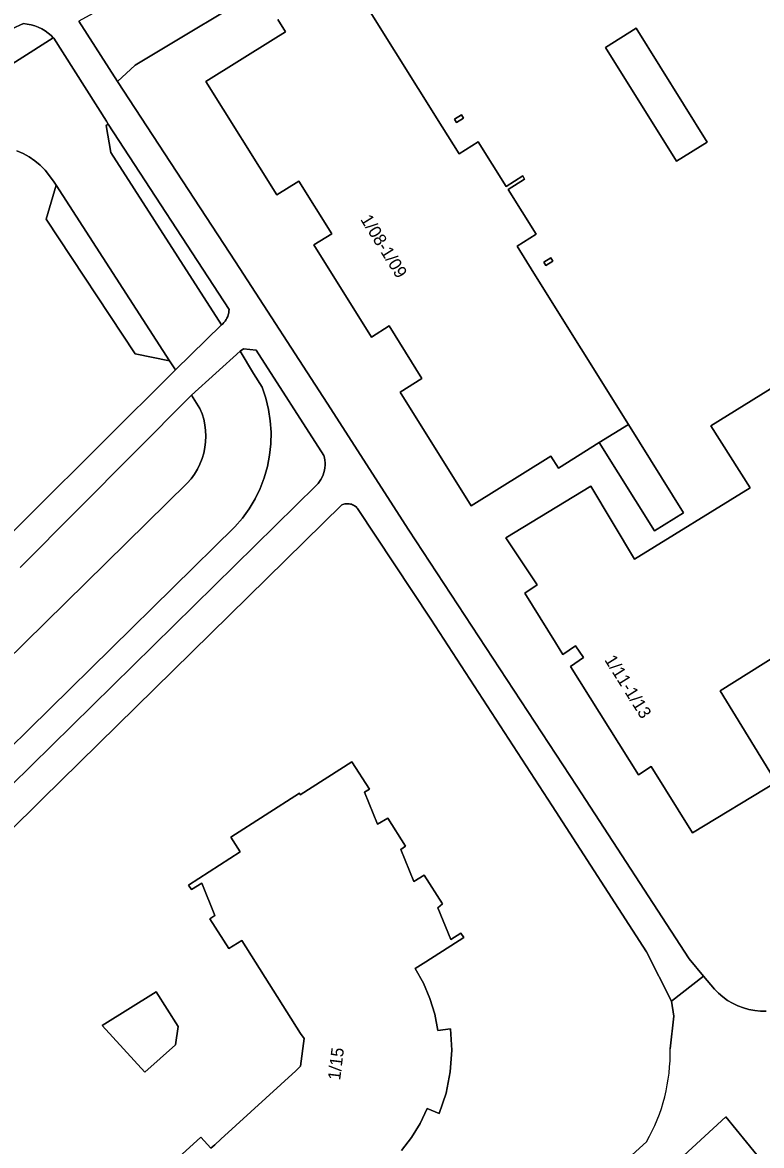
# Model space of a CAD drawing. Extents: x 162788 to 163838, y 385791 to 386523.
# Drawn here: x 163143.1 to 163202.2, y 386088.7 to 386178.4 of the extents above; entities that cross this region are included whole.
import ezdxf

# ---------------------------------------------------------------- set-up
doc = ezdxf.new("R2010")
doc.units = 0
for name, color, linetype in [('IMGEO_Berm_groen', 7, 'Continuous'), ('IMGEO_Erf', 7, 'Continuous'), ('IMGEO_Grasland_overig', 7, 'Continuous'), ('IMGEO_Pand', 7, 'Continuous'), ('IMGEO_Pand_nummerreeks', 7, 'Continuous'), ('IMGEO_Parkeervlak_open', 7, 'Continuous'), ('IMGEO_Rijbaan_lokaal_gesloten', 7, 'Continuous'), ('IMGEO_Woonerf_gesloten', 7, 'Continuous'), ('IMGEO_Woonerf_open', 7, 'Continuous')]:
    doc.layers.add(name, color=color, linetype=linetype)

msp = doc.modelspace()

# ---------------------------------------------------------------- linework, layer by layer
at = {"layer": 'IMGEO_Berm_groen'}
msp.add_lwpolyline([(163149.982, 386170.293), (163149.802, 386170.175), (163150.188, 386168.025), (163159.018, 386154.239), (163159.126, 386154.334), (163159.226, 386154.437), (163159.316, 386154.549), (163159.395, 386154.669), (163159.464, 386154.795), (163159.521, 386154.927), (163159.566, 386155.063), (163159.599, 386155.203), (163159.619, 386155.345), (163159.627, 386155.489)], close=True, dxfattribs=at)
for points in [[(163135.695, 386111.044), (163166.602, 386141.424), (163166.739, 386141.57), (163166.863, 386141.727), (163166.974, 386141.894), (163167.069, 386142.069), (163167.15, 386142.253), (163167.214, 386142.442), (163167.262, 386142.636), (163167.293, 386142.834), (163167.307, 386143.034), (163167.305, 386143.234), (163167.285, 386143.433), (163167.248, 386143.629), (163167.195, 386143.822), (163161.786, 386152.232), (163160.792, 386152.325), (163160.511, 386152.137), (163161.586, 386150.349), (163162.28, 386149.265), (163162.573, 386148.391), (163162.789, 386147.496), (163162.928, 386146.585), (163162.987, 386145.665), (163162.968, 386144.743), (163162.869, 386143.827), (163162.691, 386142.923), (163162.437, 386142.037), (163162.107, 386141.177), (163161.705, 386140.347), (163161.232, 386139.556), (163160.694, 386138.808), (163160.093, 386138.11), (163135.419, 386113.879)], [(163123.874, 386109.738), (163156.292, 386141.593), (163156.591, 386141.944), (163156.86, 386142.318), (163157.097, 386142.714), (163157.301, 386143.128), (163157.47, 386143.558), (163157.603, 386143.999), (163157.698, 386144.449), (163157.756, 386144.905), (163157.775, 386145.362), (163157.756, 386145.818), (163157.699, 386146.27), (163157.603, 386146.713), (163157.471, 386147.144), (163157.302, 386147.561), (163156.619, 386148.636), (163142.941, 386134.855)]]:
    msp.add_lwpolyline(points, dxfattribs=at)
at = {"layer": 'IMGEO_Erf'}
for points in [[(163174.351, 386188.349), (163152.119, 386175.015), (163150.727, 386173.684), (163160.137, 386159.282), (163167.48, 386147.987), (163174, 386137.852), (163187.423, 386117.375), (163196.406, 386103.576), (163197.553, 386102.198), (163198.412, 386101.166), (163198.74, 386100.837), (163199.095, 386100.537), (163199.475, 386100.269), (163199.876, 386100.033), (163200.296, 386099.833), (163200.731, 386099.67), (163201.178, 386099.544), (163201.635, 386099.457), (163202.097, 386099.409), (163202.562, 386099.401)], [(163169.112, 386182.147), (163176.671, 386170.084), (163178.028, 386167.918), (163179.55, 386168.873), (163181.774, 386165.309), (163183.101, 386166.149), (163183.247, 386165.899), (163181.929, 386165.064), (163184.16, 386161.485), (163182.654, 386160.532), (163183.998, 386158.378), (163191.539, 386146.293), (163195.946, 386139.231), (163193.633, 386137.784), (163189.218, 386144.841), (163185.946, 386142.794), (163185.335, 386143.768), (163178.973, 386139.791), (163173.302, 386148.859), (163175.048, 386149.951), (163172.438, 386154.158), (163171.012, 386153.268), (163166.412, 386160.64), (163167.837, 386161.529), (163165.202, 386165.721), (163163.456, 386164.629), (163157.776, 386173.707), (163163.154, 386177.061), (163164.137, 386177.674), (163163.53, 386178.648)], [(163137.817, 386133.231), (163155.341, 386150.644), (163154.867, 386151.379), (163152.129, 386151.937), (163145.02, 386162.683), (163145.808, 386165.423), (163145.612, 386165.726), (163144.927, 386166.624), (163144.534, 386167.01), (163144.109, 386167.36), (163143.655, 386167.671), (163143.176, 386167.941), (163142.674, 386168.168)], [(163207.82, 386130.622), (163198.88, 386125.005), (163203.35, 386117.7), (163196.672, 386113.666), (163193.356, 386118.946), (163192.347, 386118.294), (163186.911, 386126.96), (163187.943, 386127.659), (163187.326, 386128.598), (163186.314, 386127.919), (163185.726, 386128.862), (163183.269, 386132.801), (163184.264, 386133.48), (163181.739, 386137.238), (163188.543, 386141.352), (163192.027, 386135.514), (163201.283, 386141.237), (163198.119, 386146.168), (163204.791, 386150.309)], [(163194.877, 386096.402), (163195.179, 386099.002), (163194.99, 386100.199), (163192.996, 386104.134), (163185.454, 386115.822), (163175.748, 386130.733), (163169.9, 386139.568), (163169.843, 386139.633), (163169.781, 386139.694), (163169.715, 386139.75), (163169.643, 386139.799), (163169.568, 386139.843), (163169.489, 386139.879), (163169.408, 386139.909), (163169.324, 386139.932), (163169.239, 386139.948), (163169.152, 386139.957), (163169.066, 386139.958), (163168.979, 386139.952), (163168.893, 386139.939), (163168.809, 386139.918), (163168.727, 386139.891), (163168.647, 386139.856), (163144.69, 386116.333), (163116.889, 386088.826)], [(163155.599, 386087.705), (163157.375, 386089.331), (163158.182, 386088.45), (163158.481, 386088.723), (163158.978, 386089.177), (163164.955, 386094.645), (163165.343, 386095), (163165.62, 386097.207), (163165.352, 386097.62), (163160.644, 386105.045), (163159.621, 386104.421), (163158.103, 386106.796), (163158.496, 386107.051), (163157.447, 386109.635), (163156.618, 386109.126), (163156.397, 386109.483), (163160.515, 386112.142), (163159.769, 386113.313), (163165.255, 386116.817), (163165.303, 386116.703), (163169.449, 386119.331), (163170.856, 386117.142), (163170.453, 386116.896), (163171.504, 386114.352), (163172.318, 386114.817), (163173.732, 386112.592), (163173.353, 386112.334), (163174.401, 386109.77), (163175.218, 386110.268), (163176.69, 386107.982), (163176.304, 386107.663), (163177.351, 386105.139), (163178.156, 386105.644), (163178.394, 386105.293), (163175.367, 386103.35), (163174.512, 386102.801), (163175.162, 386101.65), (163175.685, 386100.428), (163176.07, 386099.155), (163176.31, 386097.855), (163177.333, 386098.001), (163177.427, 386096.286), (163177.305, 386094.559), (163176.969, 386092.861), (163176.428, 386091.231), (163175.475, 386091.614), (163174.914, 386090.429), (163174.223, 386089.306), (163173.413, 386088.264)], [(163129.316, 386031.834), (163130.711, 386032.995), (163156.731, 386056.38), (163168.437, 386066.688), (163193.001, 386088.975)]]:
    msp.add_lwpolyline(points, dxfattribs=at)
for points in [[(163197.834, 386168.858), (163195.392, 386167.335), (163189.725, 386176.426), (163192.167, 386177.948)], [(163178.365, 386170.754), (163177.803, 386170.416), (163177.635, 386170.688), (163178.2, 386171.037)], [(163185.516, 386159.33), (163184.953, 386158.995), (163184.786, 386159.268), (163185.347, 386159.61)], [(163149.491, 386098.267), (163153.804, 386100.948), (163155.569, 386098.189), (163155.34, 386096.714), (163152.891, 386094.531)]]:
    msp.add_lwpolyline(points, close=True, dxfattribs=at)
msp.add_arc((163180.704, 386096.032), 14.178, 330.15093, 1.49721, dxfattribs=at)
at = {"layer": 'IMGEO_Grasland_overig'}
msp.add_lwpolyline([(163105.896, 385959.534), (163111.404, 385963.758), (163130.396, 385976.293), (163134.062, 385978.713), (163159.928, 385999.607), (163159.543, 386000), (163138.447, 386021.548), (163206.371, 386083.102), (163206.676, 386083.379), (163205.132, 386083.984), (163204.985, 386084.042), (163200.984, 386088.924), (163199.323, 386090.951), (163185.549, 386078.284), (163151.762, 386047.67), (163133.296, 386031.516)], dxfattribs=at)
at = {"layer": 'IMGEO_Pand'}
for points in [[(163163.53, 386178.648), (163164.137, 386177.674), (163163.154, 386177.061), (163157.776, 386173.707), (163163.456, 386164.629), (163165.202, 386165.721), (163167.837, 386161.529), (163166.412, 386160.64), (163171.012, 386153.268), (163172.438, 386154.158), (163175.048, 386149.951), (163173.302, 386148.859), (163178.973, 386139.791), (163185.335, 386143.768), (163185.946, 386142.794), (163189.218, 386144.841), (163191.539, 386146.293), (163183.998, 386158.378), (163182.654, 386160.532), (163184.16, 386161.485), (163181.929, 386165.064), (163183.247, 386165.899), (163183.101, 386166.149), (163181.774, 386165.309), (163179.55, 386168.873), (163178.028, 386167.918), (163176.671, 386170.084), (163169.112, 386182.147)], [(163204.791, 386150.309), (163198.119, 386146.168), (163201.283, 386141.237), (163192.027, 386135.514), (163188.543, 386141.352), (163181.739, 386137.238), (163184.264, 386133.48), (163183.269, 386132.801), (163185.726, 386128.862), (163186.314, 386127.919), (163187.326, 386128.598), (163187.943, 386127.659), (163186.911, 386126.96), (163192.347, 386118.294), (163193.356, 386118.946), (163196.672, 386113.666), (163203.35, 386117.7), (163198.88, 386125.005), (163207.82, 386130.622)], [(163173.413, 386088.264), (163174.223, 386089.306), (163174.914, 386090.429), (163175.475, 386091.614), (163176.428, 386091.231), (163176.969, 386092.861), (163177.305, 386094.559), (163177.427, 386096.286), (163177.333, 386098.001), (163176.31, 386097.855), (163176.07, 386099.155), (163175.685, 386100.428), (163175.162, 386101.65), (163174.512, 386102.801), (163175.367, 386103.35), (163178.394, 386105.293), (163178.156, 386105.644), (163177.351, 386105.139), (163176.304, 386107.663), (163176.69, 386107.982), (163175.218, 386110.268), (163174.401, 386109.77), (163173.353, 386112.334), (163173.732, 386112.592), (163172.318, 386114.817), (163171.504, 386114.352), (163170.453, 386116.896), (163170.856, 386117.142), (163169.449, 386119.331), (163165.303, 386116.703), (163165.255, 386116.817), (163159.769, 386113.313), (163160.515, 386112.142), (163156.397, 386109.483), (163156.618, 386109.126), (163157.447, 386109.635), (163158.496, 386107.051), (163158.103, 386106.796), (163159.621, 386104.421), (163160.644, 386105.045), (163165.352, 386097.62), (163165.62, 386097.207), (163165.343, 386095), (163164.955, 386094.645), (163158.978, 386089.177), (163158.481, 386088.723), (163158.182, 386088.45), (163157.375, 386089.331), (163155.599, 386087.705)]]:
    msp.add_lwpolyline(points, dxfattribs=at)
for points in [[(163189.725, 386176.426), (163195.392, 386167.335), (163197.834, 386168.858), (163192.167, 386177.948)], [(163178.365, 386170.754), (163178.2, 386171.037), (163177.635, 386170.688), (163177.803, 386170.416)], [(163185.516, 386159.33), (163185.347, 386159.61), (163184.786, 386159.268), (163184.953, 386158.995)], [(163191.539, 386146.293), (163189.218, 386144.841), (163193.633, 386137.784), (163195.946, 386139.231)], [(163155.34, 386096.714), (163155.569, 386098.189), (163153.804, 386100.948), (163149.491, 386098.267), (163152.891, 386094.531)]]:
    msp.add_lwpolyline(points, close=True, dxfattribs=at)
at = {"layer": 'IMGEO_Parkeervlak_open'}
msp.add_lwpolyline([(163145.808, 386165.423), (163145.02, 386162.683), (163152.129, 386151.937), (163154.867, 386151.379)], close=True, dxfattribs=at)
at = {"layer": 'IMGEO_Rijbaan_lokaal_gesloten'}
for points in [[(163202.562, 386099.401), (163202.097, 386099.409), (163201.635, 386099.457), (163201.178, 386099.544), (163200.731, 386099.67), (163200.296, 386099.833), (163199.876, 386100.033), (163199.475, 386100.269), (163199.095, 386100.537), (163198.74, 386100.837), (163198.412, 386101.166), (163197.553, 386102.198), (163194.99, 386100.199), (163195.179, 386099.002), (163194.877, 386096.402)], [(163185.549, 386078.284), (163199.323, 386090.951), (163200.984, 386088.924), (163204.985, 386084.042)], [(163193.001, 386088.975), (163168.437, 386066.688), (163156.731, 386056.38), (163130.711, 386032.995), (163129.316, 386031.834)]]:
    msp.add_lwpolyline(points, dxfattribs=at)
msp.add_arc((163180.704, 386096.032), 14.178, 330.15093, 1.49721, dxfattribs=at)
at = {"layer": 'IMGEO_Woonerf_gesloten'}
for points in [[(163116.889, 386088.826), (163144.69, 386116.333), (163168.647, 386139.856), (163168.727, 386139.891), (163168.809, 386139.918), (163168.893, 386139.939), (163168.979, 386139.952), (163169.066, 386139.958), (163169.152, 386139.957), (163169.239, 386139.948), (163169.324, 386139.932), (163169.408, 386139.909), (163169.489, 386139.879), (163169.568, 386139.843), (163169.643, 386139.799), (163169.715, 386139.75), (163169.781, 386139.694), (163169.843, 386139.633), (163169.9, 386139.568), (163175.748, 386130.733), (163185.454, 386115.822), (163192.996, 386104.134), (163194.99, 386100.199), (163197.553, 386102.198), (163196.406, 386103.576), (163187.423, 386117.375), (163174, 386137.852), (163167.48, 386147.987), (163160.137, 386159.282), (163150.727, 386173.684), (163147.636, 386178.505)], [(163140.387, 386177.042), (163143.201, 386178.324), (163143.505, 386178.29), (163143.805, 386178.23), (163144.099, 386178.145), (163144.385, 386178.035), (163144.66, 386177.901), (163144.923, 386177.744), (163145.171, 386177.565), (163145.403, 386177.366), (163145.575, 386177.192), (163145.618, 386177.148), (163149.824, 386170.535), (163149.982, 386170.293), (163159.627, 386155.489), (163159.619, 386155.345), (163159.599, 386155.203), (163159.566, 386155.063), (163159.521, 386154.927), (163159.464, 386154.795), (163159.395, 386154.669), (163159.316, 386154.549), (163159.226, 386154.437), (163159.126, 386154.334), (163159.018, 386154.239), (163155.341, 386150.644), (163137.817, 386133.231)], [(163142.941, 386134.855), (163156.619, 386148.636), (163160.511, 386152.137), (163160.792, 386152.325), (163161.786, 386152.232), (163167.195, 386143.822), (163167.248, 386143.629), (163167.285, 386143.433), (163167.305, 386143.234), (163167.307, 386143.034), (163167.293, 386142.834), (163167.262, 386142.636), (163167.214, 386142.442), (163167.15, 386142.253), (163167.069, 386142.069), (163166.974, 386141.894), (163166.863, 386141.727), (163166.739, 386141.57), (163166.602, 386141.424), (163135.695, 386111.044)]]:
    msp.add_lwpolyline(points, dxfattribs=at)
at = {"layer": 'IMGEO_Woonerf_open'}
for points in [[(163174.351, 386188.349), (163176.051, 386189.368), (163180.732, 386192.184), (163178.061, 386196.569), (163176.343, 386195.547), (163167.872, 386190.449), (163167.706, 386190.356), (163167.656, 386190.325), (163155.014, 386182.729), (163151.955, 386180.913), (163147.636, 386178.505), (163150.727, 386173.684), (163152.119, 386175.015)], [(163145.575, 386177.192), (163145.403, 386177.366), (163145.171, 386177.565), (163144.923, 386177.744), (163144.66, 386177.901), (163144.385, 386178.035), (163144.099, 386178.145), (163143.805, 386178.23), (163143.505, 386178.29), (163143.201, 386178.324), (163140.387, 386177.042), (163138.136, 386176.084), (163139.831, 386173.533)]]:
    msp.add_lwpolyline(points, close=True, dxfattribs=at)
for points in [[(163142.674, 386168.168), (163143.176, 386167.941), (163143.655, 386167.671), (163144.109, 386167.36), (163144.534, 386167.01), (163144.927, 386166.624), (163145.612, 386165.726), (163145.808, 386165.423), (163154.867, 386151.379), (163155.341, 386150.644), (163159.018, 386154.239), (163150.188, 386168.025), (163149.802, 386170.175), (163149.982, 386170.293), (163149.824, 386170.535), (163145.618, 386177.148), (163145.575, 386177.192), (163139.831, 386173.533)], [(163135.419, 386113.879), (163160.093, 386138.11), (163160.694, 386138.808), (163161.232, 386139.556), (163161.705, 386140.347), (163162.107, 386141.177), (163162.437, 386142.037), (163162.691, 386142.923), (163162.869, 386143.827), (163162.968, 386144.743), (163162.987, 386145.665), (163162.928, 386146.585), (163162.789, 386147.496), (163162.573, 386148.391), (163162.28, 386149.265), (163161.586, 386150.349), (163160.511, 386152.137), (163156.619, 386148.636), (163157.302, 386147.561), (163157.471, 386147.144), (163157.603, 386146.713), (163157.699, 386146.27), (163157.756, 386145.818), (163157.775, 386145.362), (163157.756, 386144.905), (163157.698, 386144.449), (163157.603, 386143.999), (163157.47, 386143.558), (163157.301, 386143.128), (163157.097, 386142.714), (163156.86, 386142.318), (163156.591, 386141.944), (163156.292, 386141.593), (163123.874, 386109.738)]]:
    msp.add_lwpolyline(points, dxfattribs=at)

# ---------------------------------------------------------------- texts
at = {"layer": 'IMGEO_Pand_nummerreeks'}
for s, rotation, p in [('1/08-1/09', 301.89062, (163170.092, 386162.679)), ('1/11-1/13', 302.07437, (163189.597, 386127.479)), ('1/15', 83.01585, (163168.507, 386093.849))]:
    msp.add_text(s, height=1, rotation=rotation, dxfattribs=at).set_placement(p)

doc.saveas('drawing.dxf')
